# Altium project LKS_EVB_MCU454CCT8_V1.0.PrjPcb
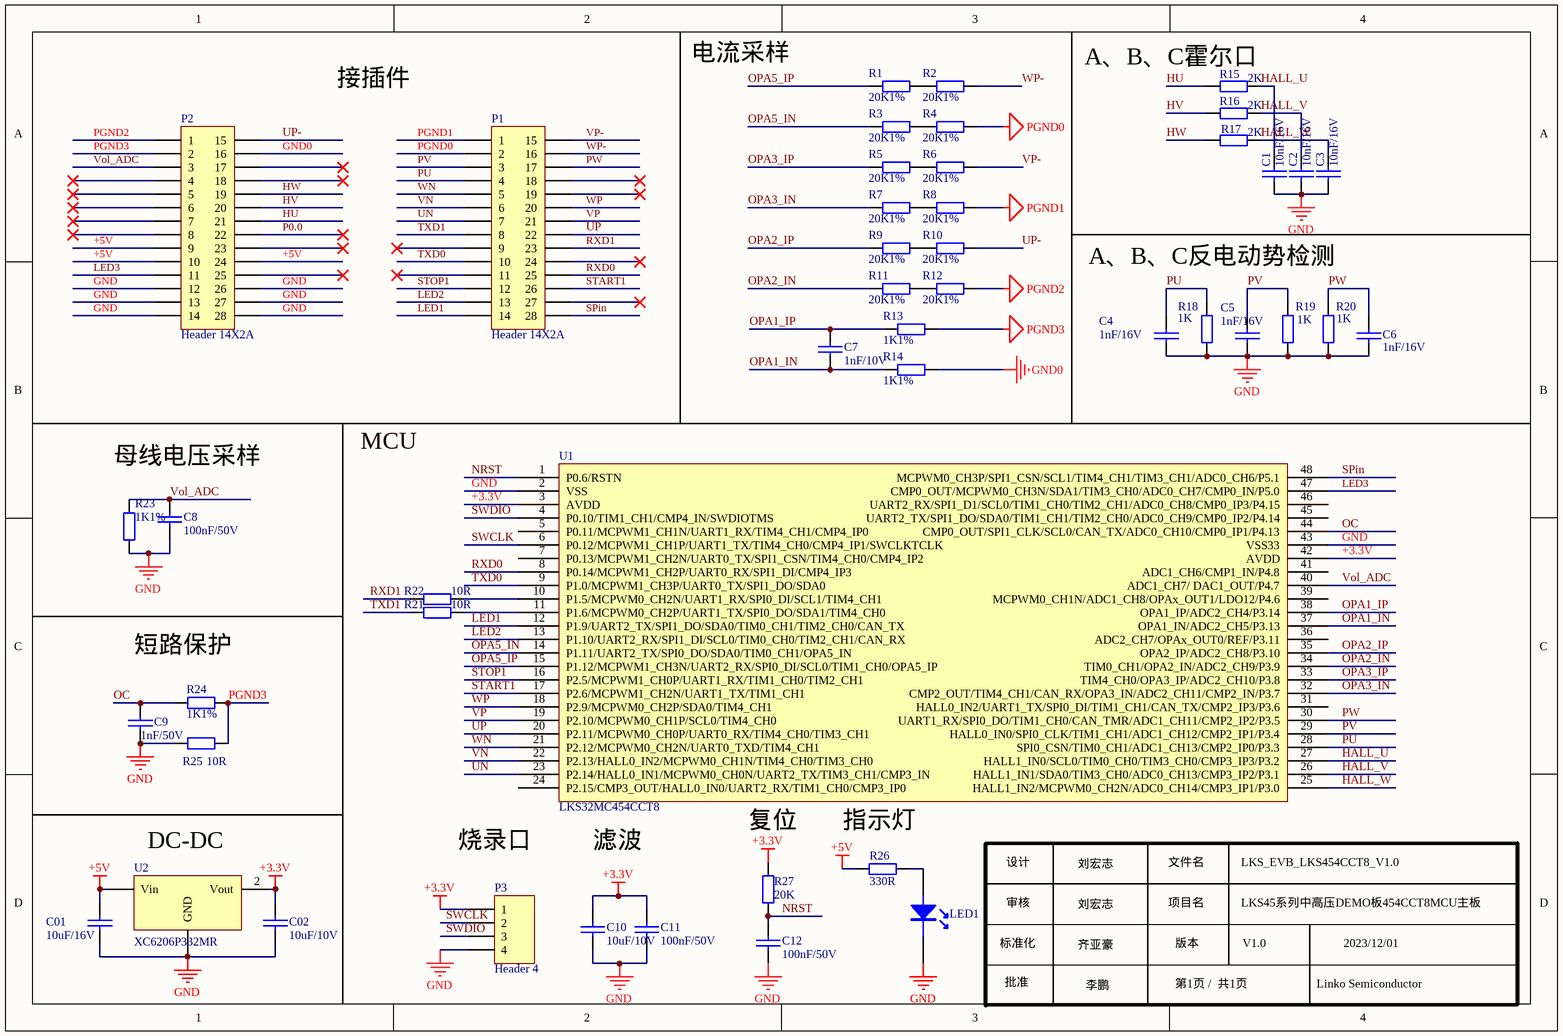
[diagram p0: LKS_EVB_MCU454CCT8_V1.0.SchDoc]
1 sheet, 47 parts. Net scope: global (net labels, ports and power ports of the same name join across sheets).
Board file: LKS_EVB_MCU454CCT8_V1.0.PcbDoc

## Sheet LKS_EVB_MCU454CCT8_V1.0.SchDoc
size A4; SheetNumber: 1; SheetTotal: 1

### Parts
C1  10nF/16V  [0603C]
C01  10uF/16V  [0603C]
C2  10nF/16V  [0603C]
C02  10uF/10V  [0603C]
C3  10nF/16V  [0603C]
C4  1nF/16V  [0603C]
C5  1nF/16V  [0603C]
C6  1nF/16V  [0603C]
C7  1nF/10V  [0603C]
C8  100nF/50V  [0603C]
C9  1nF/50V  [0603C]
C10  10uF/10V  [0603C]
C11  100nF/50V  [0603C]
C12  100nF/50V  [0603C]
LED1  LED  [LED 0603R]  (value not drawn)
P1  Header 14X2A  [HDR 2X14 顶层]
P2  Header 14X2A  [HDR 2X14 顶层]
P3  Header 4  [HDR 1X4]
R1  20K1%  [0603R]
R2  20K1%  [0603R]
R3  20K1%  [0603R]
R4  20K1%  [0603R]
R5  20K1%  [0603R]
R6  20K1%  [0603R]
R7  20K1%  [0603R]
R8  20K1%  [0603R]
R9  20K1%  [0603R]
R10  20K1%  [0603R]
R11  20K1%  [0603R]
R12  20K1%  [0603R]
R13  1K1%  [0603R]
R14  1K1%  [0603R]
R15  2K  [0603R]
R16  2K  [0603R]
R17  2K  [0603R]
R18  1K  [0603R]
R19  1K  [0603R]
R20  1K  [0603R]
R21  10R  [0603R]
R22  10R  [0603R]
R23  1K1%  [0603R]
R24  1K1%  [0603R]
R25  10R  [0603R]
R26  330R  [0603R]
R27  20K  [0603R]
U1  LKS32MC454CCT8  [TQFP48]
U2  XC6206P332MR  [SOT-23]

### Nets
+3.3V: C02.2 C10.2 C11.2 P3.1 R27.2 U1.3(AVDD) U1.42(AVDD) U2.2(Vout)
+5V: C01.2 P2.9 P2.10 P2.24 R26.1 U2.3(Vin)
GND: C01.1 C1.2 C02.1 C2.2 C3.2 C4.2 C5.2 C6.2 C8.1 C9.1 C10.1 C11.1 C12.2 LED1.2(K) P2.12 P2.13 P2.14 P2.26 P2.27 P2.28 P3.4 R18.2 R19.2 R20.2 R23.1 R25.2 U1.2(VSS) U1.43(VSS33) U2.1(GND)
GND0: P2.16 R14.1
PGND0: P1.2 R4.1
PGND1: P1.1 R8.1
PGND2: P2.1 R12.1
PGND3: P2.2 R13.1 R24.2 R25.1
HALL_U: C1.1 R15.2 U1.27(HALL1_IN0/SCL0/TIM0_CH0/TIM3_CH0/CMP3_IP3/P3.2)
HALL_V: C2.1 R16.2 U1.26(HALL1_IN1/SDA0/TIM3_CH0/ADC0_CH13/CMP3_IP2/P3.1)
HALL_W: C3.1 R17.2 U1.25(HALL1_IN2/MCPWM0_CH2N/ADC0_CH14/CMP3_IP1/P3.0)
HU: P2.21 R15.1
HV: P2.20 R16.1
HW: P2.19 R17.1
LED1: P1.14 U1.12(P1.9/UART2_TX/SPI1_DO/SDA0/TIM0_CH1/TIM2_CH0/CAN_TX)
LED2: P1.13 U1.13(P1.10/UART2_RX/SPI1_DI/SCL0/TIM0_CH0/TIM2_CH1/CAN_RX)
LED3: P2.11 U1.47(CMP0_OUT/MCPWM0_CH3N/SDA1/TIM3_CH0/ADC0_CH7/CMP0_IN/P5.0)
NRST: C12.1 R27.1 U1.1(P0.6/RSTN)
OC: C9.2 R24.1 U1.44(CMP0_OUT/SPI1_CLK/SCL0/CAN_TX/ADC0_CH10/CMP0_IP1/P4.13)
OPA1_IN: C7.2 R14.2 U1.37(OPA1_IN/ADC2_CH5/P3.13)
OPA1_IP: C7.1 R13.2 U1.38(OPA1_IP/ADC2_CH4/P3.14)
OPA2_IN: R11.2 U1.34(TIM0_CH1/OPA2_IN/ADC2_CH9/P3.9)
OPA2_IP: R9.2 U1.35(OPA2_IP/ADC2_CH8/P3.10)
OPA3_IN: R7.2 U1.32(CMP2_OUT/TIM4_CH1/CAN_RX/OPA3_IN/ADC2_CH11/CMP2_IN/P3.7)
OPA3_IP: R5.2 U1.33(TIM4_CH0/OPA3_IP/ADC2_CH10/P3.8)
OPA5_IN: R3.2 U1.14(P1.11/UART2_TX/SPI0_DO/SDA0/TIM0_CH1/OPA5_IN)
OPA5_IP: R1.2 U1.15(P1.12/MCPWM1_CH3N/UART2_RX/SPI0_DI/SCL0/TIM1_CH0/OPA5_IP)
P0.0: P2.22
PU: C4.1 P1.4 R18.1 U1.28(SPI0_CSN/TIM0_CH1/ADC1_CH13/CMP2_IP0/P3.3)
PV: C5.1 P1.3 R19.1 U1.29(HALL0_IN0/SPI0_CLK/TIM1_CH1/ADC1_CH12/CMP2_IP1/P3.4)
PW: C6.1 P1.17 R20.1 U1.30(UART1_RX/SPI0_DO/TIM1_CH0/CAN_TMR/ADC1_CH11/CMP2_IP2/P3.5)
RXD0: P1.25 U1.8(P0.14/MCPWM1_CH2P/UART0_RX/SPI1_DI/CMP4_IP3)
RXD1: P1.23 R22.2
SPin: P1.28 U1.48(MCPWM0_CH3P/SPI1_CSN/SCL1/TIM4_CH1/TIM3_CH1/ADC0_CH6/P5.1)
START1: P1.26 U1.17(P2.6/MCPWM1_CH2N/UART1_TX/TIM1_CH1)
STOP1: P1.12 U1.16(P2.5/MCPWM1_CH0P/UART1_RX/TIM1_CH0/TIM2_CH1)
SWCLK: P3.2 U1.6(P0.12/MCPWM1_CH1P/UART1_TX/TIM4_CH0/CMP4_IP1/SWCLKTCLK)
SWDIO: P3.3 U1.4(P0.10/TIM1_CH1/CMP4_IN/SWDIOTMS)
TXD0: P1.10 U1.9(P1.0/MCPWM1_CH3P/UART0_TX/SPI1_DO/SDA0)
TXD1: P1.8 R21.1
UN: P1.7 U1.23(P2.14/HALL0_IN1/MCPWM0_CH0N/UART2_TX/TIM3_CH1/CMP3_IN)
UP: P1.22 U1.20(P2.11/MCPWM0_CH0P/UART0_RX/TIM4_CH0/TIM3_CH1)
UP-: P2.15 R10.1
VN: P1.6 U1.22(P2.13/HALL0_IN2/MCPWM0_CH1N/TIM4_CH0/TIM3_CH0)
Vol_ADC: C8.2 P2.3 R23.2 U1.40(ADC1_CH7/_DAC1_OUT/P4.7)
VP: P1.21 U1.19(P2.10/MCPWM0_CH1P/SCL0/TIM4_CH0)
VP-: P1.15 R6.1
WN: P1.5 U1.21(P2.12/MCPWM0_CH2N/UART0_TXD/TIM4_CH1)
WP: P1.20 U1.18(P2.9/MCPWM0_CH2P/SDA0/TIM4_CH1)
WP-: P1.16 R2.1
NetLED1_1: LED1.1(A) R26.2
NetR1_1: R1.1 R2.2
NetR3_1: R3.1 R4.2
NetR5_1: R5.1 R6.2
NetR7_1: R7.1 R8.2
NetR9_1: R9.1 R10.2
NetR11_1: R11.1 R12.2
NetR21_2: R21.2 U1.11(P1.6/MCPWM0_CH2P/UART1_TX/SPI0_DO/SDA1/TIM4_CH0)
NetR22_1: R22.1 U1.10(P1.5/MCPWM0_CH2N/UART1_RX/SPI0_DI/SCL1/TIM4_CH1)

Not connected (* = marked no-connect by the designer): P1 9* 11* 18* 19* 24* 27*; P2 4* 5* 6* 7* 8* 17* 18* 23* 25*; U1 5(P0.11/MCPWM1_CH1N/UART1_RX/TIM4_CH1/CMP4_IP0) 7(P0.13/MCPWM1_CH2N/UART0_TX/SPI1_CSN/TIM4_CH0/CMP4_IP2) 24(P2.15/CMP3_OUT/HALL0_IN0/UART2_RX/TIM1_CH0/CMP3_IP0) 31(HALL0_IN2/UART1_TX/SPI0_DI/TIM1_CH1/CAN_TX/CMP2_IP3/P3.6) 36(ADC2_CH7/OPAx_OUT0/REF/P3.11) 39(MCPWM0_CH1N/ADC1_CH8/OPAx_OUT1/LDO12/P4.6) 41(ADC1_CH6/CMP1_IN/P4.8) 45(UART2_TX/SPI1_DO/SDA0/TIM1_CH1/TIM2_CH0/ADC0_CH9/CMP0_IP2/P4.14) 46(UART2_RX/SPI1_D1/SCL0/TIM1_CH0/TIM2_CH1/ADC0_CH8/CMP0_IP3/P4.15)

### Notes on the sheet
- 接插件
- 电流采样
- A、B、C霍尔口
- A、B、C反电动势检测
- MCU
- 母线电压采样
- 短路保护
- (near U2) DC-DC
- 烧录口
- (near U1) 滤波
- (near U1) 复位
- 指示灯
- 设计
- 审核
- 刘宏志
- 文件名
- 项目名
- LKS_EVB_LKS454CCT8_V1.0
- LKS45系列中高压DEMO板454CCT8MCU主板
- 标准化
- 批准
- 齐亚豪
- 李鹏
- 版本
- 第1页 /  共1页
- V1.0
- Linko Semiconductor
- 2023/12/01

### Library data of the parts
C1-C6 = CAP: Capacitor
C01 C02 C7-C12 = C: Capacitor
LED1 = LED: LED_Light
P1 P2 = Header 14X2A: Header, 14-Pin, Dual row
P3 = Header 4: Header, 4-Pin
R1-R25 R27 = Res: Resistor; Value: K
R26 = Res: Resistor; Value: 330
U1 = LKS32MC454CCT8: 芯片
U2 = 7805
